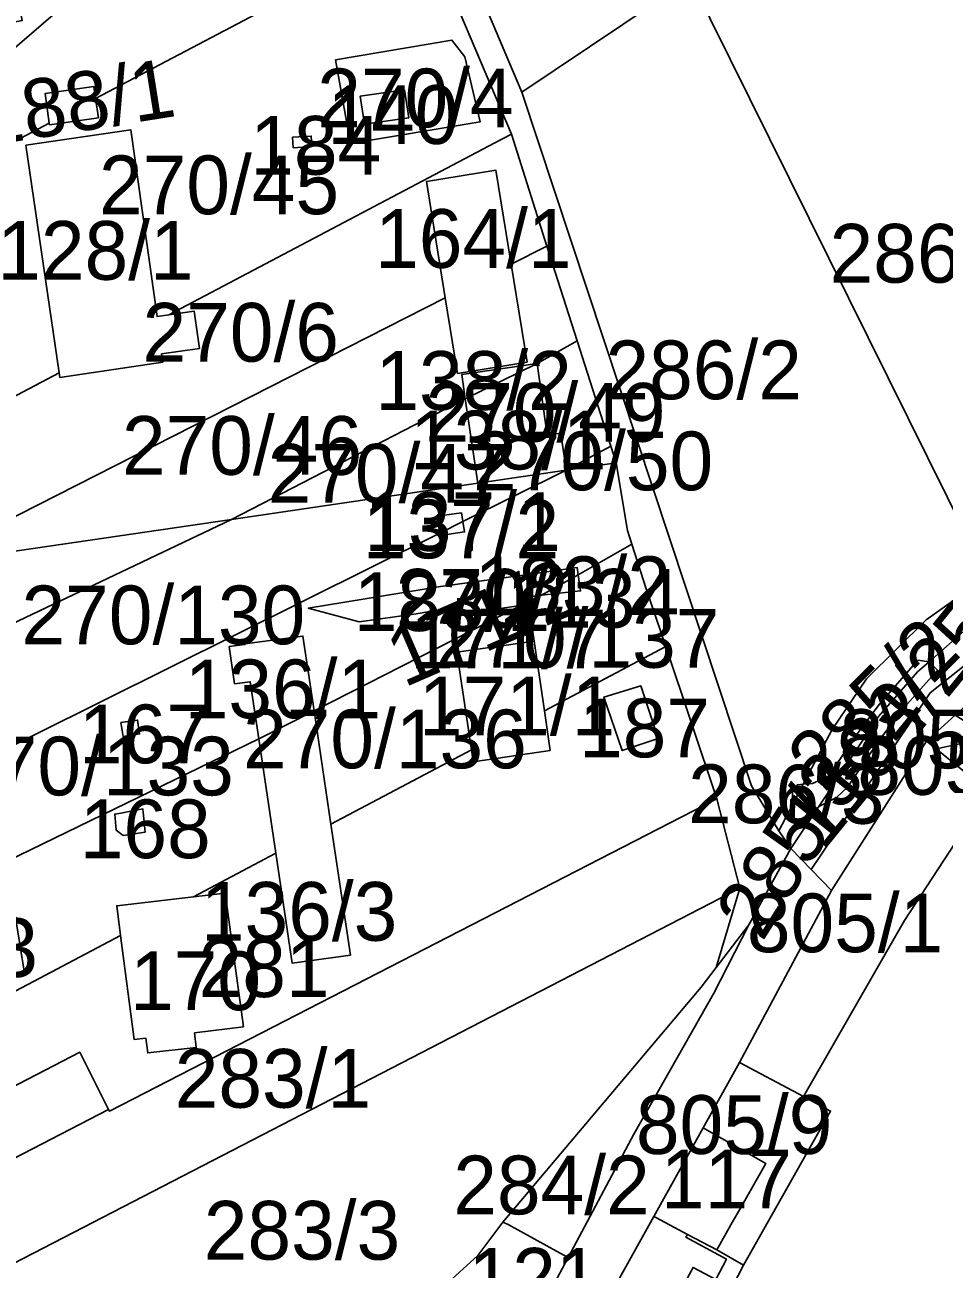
# Model space of a CAD drawing. Extents: x -623250 to -619626, y -1079612 to -1075424.
# Drawn here: x -621383.5 to -621226.9, y -1076913.6 to -1076701.7 of the extents above; entities that cross this region are included whole.
import ezdxf

# ---------------------------------------------------------------- set-up
doc = ezdxf.new("R2010")
doc.units = 0
for name, color, linetype in [('Hranice převzatá (k_ú_Džbánov - vnitřní obvod)', 7, 'Continuous'), ('Hranice šetřená (k_ú_Džbánov - vnitřní obvod)', 7, 'Continuous'), ('Parcela nároku', 7, 'Continuous'), ('Parcelní číslo', 7, 'Continuous'), ('Silnice III_35719', 7, 'Continuous')]:
    doc.layers.add(name, color=color, linetype=linetype)

msp = doc.modelspace()

# ---------------------------------------------------------------- linework, layer by layer
at = {"layer": 'Hranice převzatá (k_ú_Džbánov - vnitřní obvod)'}
msp.add_line((-621276.85, -1076943.57), (-621261.07, -1076912.95), dxfattribs=at)
msp.add_lwpolyline([(-621298.85, -1076713.1), (-621270.08, -1076693.81), (-621236.65, -1076671.5)], dxfattribs=at)
at = {"layer": 'Hranice šetřená (k_ú_Džbánov - vnitřní obvod)'}
msp.add_lwpolyline([(-621298.85, -1076713.1), (-621259.7, -1076831.32), (-621255.05, -1076838.97), (-621253, -1076841.99), (-621246.1, -1076849.15), (-621229.91, -1076823.66), (-621228.23, -1076825.01), (-621219.28, -1076832.25), (-621233.62, -1076854.22), (-621250.86, -1076884.25), (-621246.23, -1076886.72), (-621261.07, -1076912.95)], dxfattribs=at)
at = {"layer": 'Parcela nároku'}
for points in [[(-621322.96, -1076681.57), (-621319.95, -1076687.05), (-621371.44, -1076714.22), (-621371.74, -1076712.18), (-621380.06, -1076713.37), (-621379.35, -1076718.39), (-621402.49, -1076730.6), (-621403.83, -1076721.46), (-621388.56, -1076708.39), (-621376.66, -1076698.2), (-621392.01, -1076624.26), (-621356.72, -1076606.72), (-621328.57, -1076658.55), (-621315.63, -1076684.78), (-621316.6, -1076685.28), (-621319.64, -1076679.74)], [(-621388.71, -1076669.32), (-621390.43, -1076669.67), (-621383.95, -1076700.92), (-621413.69, -1076707.06), (-621426.54, -1076645.01), (-621426.15, -1076644.93), (-621426.9, -1076641.3), (-621443.58, -1076649.82), (-621442.17, -1076653.36), (-621427.19, -1076692.17), (-621425.37, -1076698.46), (-621424.67, -1076704.93), (-621425.04, -1076706.31), (-621423.47, -1076709.46), (-621412.67, -1076711.87), (-621388.56, -1076708.39), (-621376.66, -1076698.2), (-621392.01, -1076624.26), (-621418.24, -1076637.08), (-621412.96, -1076635.98), (-621411.73, -1076641.95), (-621396.81, -1076638.86), (-621391.28, -1076665.56), (-621389.61, -1076665.22)], [(-621310.32, -1076647.1), (-621318.13, -1076650.49), (-621326.18, -1076653.91), (-621314.99, -1076675.01), (-621298.85, -1076713.1), (-621270.08, -1076693.81), (-621273.77, -1076685.85), (-621291.69, -1076697.6), (-621297.85, -1076688.2), (-621290.86, -1076683.66), (-621286.12, -1076690.97), (-621282.78, -1076688.79)], [(-621182.7, -1076775.26), (-621234.22, -1076669.88), (-621236.65, -1076671.5), (-621270.08, -1076693.81), (-621219.61, -1076795.68)], [(-621319.95, -1076687.05), (-621319.59, -1076687.71), (-621316.26, -1076685.88), (-621316.6, -1076685.28), (-621315.63, -1076684.78), (-621300.62, -1076720.28), (-621303.43, -1076721.77), (-621358.98, -1076751.06), (-621360.99, -1076751.34), (-621365.44, -1076719.56), (-621383.33, -1076722.15), (-621377.65, -1076760.91), (-621397.07, -1076771.16), (-621402.49, -1076730.6), (-621379.35, -1076718.39), (-621379.3, -1076718.68), (-621370.98, -1076717.49), (-621371.44, -1076714.22)], [(-621270.08, -1076693.81), (-621298.85, -1076713.1), (-621259.7, -1076831.32), (-621255.05, -1076838.97), (-621252.76, -1076834.62), (-621252.74, -1076832.26), (-621251.88, -1076831.12), (-621250.88, -1076831.04), (-621245.98, -1076821.72), (-621240.09, -1076813.05), (-621229.96, -1076803.04), (-621219.61, -1076795.68)], [(-621308.54, -1076707.11), (-621305.93, -1076718.15), (-621328.01, -1076721.86), (-621330.58, -1076707.59), (-621310.75, -1076704.26)], [(-621330.58, -1076707.59), (-621328.01, -1076721.86), (-621305.93, -1076718.15), (-621308.54, -1076707.11), (-621310.75, -1076704.26)], [(-621371.44, -1076714.22), (-621370.98, -1076717.49), (-621379.3, -1076718.68), (-621379.35, -1076718.39), (-621380.06, -1076713.37), (-621371.74, -1076712.18)], [(-621318.83, -1076712.73), (-621318.11, -1076717.52), (-621325.64, -1076718.58), (-621326.4, -1076713.81)], [(-621325.64, -1076718.58), (-621326.4, -1076713.81), (-621318.83, -1076712.73), (-621318.11, -1076717.52)], [(-621294.55, -1076739.35), (-621300.62, -1076720.28), (-621303.43, -1076721.77), (-621358.98, -1076751.06), (-621354.64, -1076750.45), (-621353.76, -1076756.8), (-621360.2, -1076757.7), (-621360, -1076759.14), (-621377.55, -1076761.72), (-621377.65, -1076760.91), (-621397.07, -1076771.16), (-621395.87, -1076781.11), (-621394.56, -1076790.17), (-621311.88, -1076748.16), (-621315.1, -1076728.34), (-621303.25, -1076726.41), (-621300.64, -1076742.44)], [(-621354.64, -1076750.45), (-621353.76, -1076756.8), (-621360.2, -1076757.7), (-621360, -1076759.14), (-621377.55, -1076761.72), (-621377.65, -1076760.91), (-621383.33, -1076722.15), (-621365.44, -1076719.56), (-621360.99, -1076751.34), (-621358.98, -1076751.06)], [(-621334.72, -1076720.59), (-621334.6, -1076722.37), (-621337.79, -1076722.59), (-621337.89, -1076720.81)], [(-621337.79, -1076722.59), (-621334.6, -1076722.37), (-621334.72, -1076720.59), (-621337.89, -1076720.81)], [(-621297.93, -1076759.11), (-621300.64, -1076742.44), (-621303.25, -1076726.41), (-621315.1, -1076728.34), (-621311.88, -1076748.16), (-621309.78, -1076761.04)], [(-621309.78, -1076761.04), (-621297.93, -1076759.11), (-621300.64, -1076742.44), (-621294.55, -1076739.35), (-621289.41, -1076755.49), (-621296.21, -1076759.36), (-621309.08, -1076761.24), (-621308.47, -1076765.34), (-621348.32, -1076785.92), (-621394.2, -1076792.65), (-621394.56, -1076790.17), (-621311.88, -1076748.16)], [(-621296.21, -1076759.36), (-621289.41, -1076755.49), (-621283.67, -1076773.41), (-621291.29, -1076777.54), (-621292.22, -1076771.24), (-621294.53, -1076771.57)], [(-621309.08, -1076761.24), (-621296.21, -1076759.36), (-621308.47, -1076765.34)], [(-621296.21, -1076759.36), (-621294.53, -1076771.57), (-621292.22, -1076771.24), (-621291.29, -1076777.54), (-621293.61, -1076777.88), (-621306.32, -1076779.74), (-621308.47, -1076765.34)], [(-621348.32, -1076785.92), (-621308.47, -1076765.34), (-621306.32, -1076779.74)], [(-621291.29, -1076777.54), (-621283.67, -1076773.41), (-621282.75, -1076776.26)], [(-621348.32, -1076785.92), (-621306.32, -1076779.74), (-621293.61, -1076777.88), (-621291.29, -1076777.54), (-621308.88, -1076786.29), (-621309.12, -1076784.79), (-621313.33, -1076785.36), (-621312.82, -1076788.25), (-621393.46, -1076828.35), (-621394.99, -1076818.77), (-621390.79, -1076818.12), (-621391.71, -1076812.19), (-621395.9, -1076812.86), (-621409.24, -1076814.91)], [(-621308.88, -1076786.29), (-621309.12, -1076784.79), (-621313.33, -1076785.36), (-621312.82, -1076788.25)], [(-621406.62, -1076795.93), (-621402.17, -1076793.81), (-621398.87, -1076793.33), (-621394.2, -1076792.65), (-621348.32, -1076785.92), (-621409.24, -1076814.91), (-621431.24, -1076827.04), (-621432.51, -1076818.29), (-621437.84, -1076818.95), (-621449.89, -1076820.81), (-621447.66, -1076836.1), (-621458.65, -1076841.61), (-621461.29, -1076823.62), (-621412.18, -1076798.59), (-621412.05, -1076799.5), (-621406.26, -1076798.56)], [(-621308.59, -1076788.05), (-621308.88, -1076786.29), (-621312.82, -1076788.25), (-621312.75, -1076788.66)], [(-621277.63, -1076797.72), (-621274.32, -1076807.57), (-621294.99, -1076818.54), (-621296.72, -1076806.64), (-621297.63, -1076800.41), (-621297.69, -1076799.94), (-621295.5, -1076798.83), (-621288.82, -1076798.08), (-621289.22, -1076795.36), (-621280.1, -1076790.12)], [(-621296.99, -1076795.19), (-621312.68, -1076797.31), (-621335.21, -1076801.02), (-621326.55, -1076803.37), (-621316.86, -1076802.02), (-621312.17, -1076801.19), (-621310.98, -1076801.02), (-621310.83, -1076802.29), (-621298.99, -1076800.6), (-621297.63, -1076800.41), (-621297.69, -1076799.94), (-621297.79, -1076799.13), (-621296.46, -1076798.94), (-621295.5, -1076798.83), (-621289.22, -1076795.36), (-621289.41, -1076794.08)], [(-621288.82, -1076798.08), (-621289.22, -1076795.36), (-621295.5, -1076798.83)], [(-621250.88, -1076831.04), (-621245.98, -1076821.72), (-621240.09, -1076813.05), (-621229.96, -1076803.04), (-621219.61, -1076795.68), (-621217.62, -1076799.73), (-621229.47, -1076810.15), (-621231.36, -1076809.88), (-621237.9, -1076817.41), (-621241.71, -1076822.45), (-621246.57, -1076829.67), (-621249.32, -1076830.92)], [(-621297.79, -1076799.13), (-621296.46, -1076798.94), (-621295.5, -1076798.83), (-621297.69, -1076799.94)], [(-621310.83, -1076802.29), (-621298.99, -1076800.6), (-621310.23, -1076806.32)], [(-621310.23, -1076806.32), (-621298.99, -1076800.6), (-621297.63, -1076800.41), (-621296.72, -1076806.64), (-621309.9, -1076808.54)], [(-621346.03, -1076807.08), (-621336.12, -1076805.78), (-621334.23, -1076818.52), (-621343.65, -1076823.28), (-621345.1, -1076813.57), (-621347.76, -1076813.91), (-621348.68, -1076807.58), (-621346.01, -1076807.23)], [(-621307.42, -1076825.14), (-621309.9, -1076808.54), (-621310.23, -1076806.32), (-621334.23, -1076818.52), (-621331.36, -1076837.85)], [(-621294.99, -1076818.54), (-621294.01, -1076825.27), (-621307.11, -1076827.22), (-621307.42, -1076825.14), (-621309.9, -1076808.54), (-621296.72, -1076806.64)], [(-621241.71, -1076822.45), (-621246.57, -1076829.67), (-621249.32, -1076830.92), (-621250.88, -1076831.04), (-621252.76, -1076834.62), (-621255.05, -1076838.97), (-621253, -1076841.99), (-621248.24, -1076834.81), (-621238.1, -1076819.51), (-621231.41, -1076811.86), (-621229.47, -1076810.15), (-621231.36, -1076809.88), (-621237.9, -1076817.41)], [(-621231.41, -1076811.86), (-621229.47, -1076810.15), (-621228.04, -1076811.58), (-621233.71, -1076817.96), (-621237.89, -1076823.44), (-621243.38, -1076831.55), (-621245.25, -1076833.3), (-621248.24, -1076834.81), (-621238.1, -1076819.51)], [(-621275.6, -1076823.26), (-621278.55, -1076814.27), (-621284.86, -1076816.17), (-621281.73, -1076825.28)], [(-621281.73, -1076825.28), (-621275.6, -1076823.26), (-621278.55, -1076814.27), (-621284.86, -1076816.17)], [(-621328.05, -1076860.12), (-621331.36, -1076837.85), (-621334.23, -1076818.52), (-621343.65, -1076823.28), (-621340.75, -1076842.78), (-621337.96, -1076861.51)], [(-621364.3, -1076820.1), (-621367.15, -1076820.51), (-621366.78, -1076822.87), (-621363.96, -1076822.46)], [(-621366.78, -1076822.87), (-621363.96, -1076822.46), (-621364.3, -1076820.1), (-621367.15, -1076820.51)], [(-621229.91, -1076823.66), (-621225, -1076819.24), (-621221.18, -1076821.67), (-621223.92, -1076824.07), (-621228.23, -1076825.01)], [(-621221.18, -1076821.67), (-621223.92, -1076824.07), (-621228.23, -1076825.01), (-621219.28, -1076832.25), (-621214.06, -1076826.2)], [(-621442.1, -1076874.3), (-621462.22, -1076885.24), (-621454.35, -1076902.86), (-621367.2, -1076856.77), (-621367.86, -1076851.73), (-621354.77, -1076850.19), (-621340.75, -1076842.78), (-621343.65, -1076823.28), (-621386.62, -1076844.18), (-621383.59, -1076863.23), (-621387.8, -1076863.85), (-621401.16, -1076865.82), (-621403.2, -1076852.98), (-621425.73, -1076865.1), (-621423.89, -1076877.78), (-621429.15, -1076878.6), (-621441.23, -1076880.28)], [(-621229.91, -1076823.66), (-621228.23, -1076825.01), (-621219.28, -1076832.25), (-621233.62, -1076854.22), (-621250.86, -1076884.25), (-621261.77, -1076878.43), (-621246.1, -1076849.15)], [(-621250.88, -1076831.04), (-621251.88, -1076831.12), (-621252.74, -1076832.26), (-621252.76, -1076834.62)], [(-621265.61, -1076833.49), (-621261.7, -1076848.72), (-621388.91, -1076914.43), (-621400.8, -1076920.49), (-621408.16, -1076906.52), (-621369.25, -1076886.43), (-621369.11, -1076886.7)], [(-621363.39, -1076835.24), (-621367.13, -1076835.94), (-621368.18, -1076836.1), (-621367.92, -1076838.85), (-621366.76, -1076839.78), (-621362.98, -1076839.17)], [(-621368.18, -1076836.1), (-621367.92, -1076838.85), (-621366.76, -1076839.78), (-621362.98, -1076839.17), (-621363.39, -1076835.24), (-621367.13, -1076835.94)], [(-621388.91, -1076914.43), (-621261.7, -1076848.72), (-621265.74, -1076862.26), (-621268.27, -1076865.58), (-621302.1, -1076905.64), (-621306.34, -1076911.31), (-621320.09, -1076923.81), (-621321.03, -1076924.46), (-621358.9, -1076950.67), (-621371.51, -1076935.3)], [(-621354.31, -1076875.88), (-621354.59, -1076873.38), (-621346.27, -1076872.33), (-621349.37, -1076849.56), (-621354.77, -1076850.19), (-621367.86, -1076851.73), (-621367.2, -1076856.77), (-621364.88, -1076874.53), (-621362.88, -1076874.3), (-621362.57, -1076876.81)], [(-621302.1, -1076905.64), (-621268.27, -1076865.58), (-621265.74, -1076862.26), (-621260.18, -1076854.95), (-621266.21, -1076866.74), (-621279.76, -1076890.66), (-621290.94, -1076911.65), (-621292.93, -1076910.56), (-621301.18, -1076906.02)], [(-621374.14, -1076876.68), (-621369.25, -1076886.43), (-621408.16, -1076906.52), (-621418.09, -1076911.65), (-621423.06, -1076902.04)], [(-621265.64, -1076910.36), (-621263.22, -1076906.1), (-621261.31, -1076902.73), (-621257.27, -1076895.61), (-621262.24, -1076892.79), (-621267.25, -1076889.96), (-621267.95, -1076889.56), (-621261.77, -1076878.43), (-621250.86, -1076884.25), (-621246.23, -1076886.72), (-621261.07, -1076912.95)], [(-621262.24, -1076892.79), (-621257.27, -1076895.61), (-621261.31, -1076902.73), (-621263.22, -1076906.1), (-621265.64, -1076910.36), (-621270.64, -1076907.72), (-621275.91, -1076904.88), (-621276.33, -1076904.65), (-621267.95, -1076889.56), (-621267.25, -1076889.96)], [(-621263.97, -1076911.91), (-621270.87, -1076908.16), (-621270.64, -1076907.72), (-621275.91, -1076904.88), (-621276.33, -1076904.65), (-621286.38, -1076922.74), (-621285.9, -1076923.02), (-621277.33, -1076927.74), (-621271.34, -1076916.49), (-621269.65, -1076913.33), (-621265.81, -1076915.39)], [(-621320.09, -1076923.81), (-621321.03, -1076924.46), (-621298.1, -1076925.1), (-621290.94, -1076911.65), (-621292.93, -1076910.56), (-621301.18, -1076906.02), (-621302.1, -1076905.64), (-621306.34, -1076911.31)], [(-621293.22, -1076935.57), (-621286.38, -1076922.74), (-621285.9, -1076923.02), (-621277.33, -1076927.74), (-621271.34, -1076916.49), (-621269.65, -1076913.33), (-621265.81, -1076915.39), (-621263.97, -1076911.91), (-621270.87, -1076908.16), (-621270.64, -1076907.72), (-621265.64, -1076910.36), (-621261.07, -1076912.95), (-621276.85, -1076943.57), (-621281.03, -1076941.69)]]:
    msp.add_lwpolyline(points, close=True, dxfattribs=at)
for points in [[(-621314.99, -1076675.01), (-621298.85, -1076713.1), (-621259.7, -1076831.32), (-621255.05, -1076838.97), (-621253, -1076841.99), (-621260.18, -1076854.95), (-621265.74, -1076862.26), (-621261.7, -1076848.72), (-621265.61, -1076833.49), (-621274.32, -1076807.57), (-621277.63, -1076797.72), (-621280.1, -1076790.12), (-621280.86, -1076787.78), (-621282.75, -1076776.26), (-621283.67, -1076773.41), (-621289.41, -1076755.49), (-621294.55, -1076739.35), (-621300.62, -1076720.28), (-621315.63, -1076684.78)], [(-621298.1, -1076925.1), (-621290.94, -1076911.65), (-621279.76, -1076890.66), (-621266.21, -1076866.74), (-621260.18, -1076854.95), (-621253, -1076841.99), (-621248.24, -1076834.81), (-621245.25, -1076833.3), (-621243.38, -1076831.55), (-621237.89, -1076823.44), (-621233.71, -1076817.96), (-621228.04, -1076811.58), (-621229.47, -1076810.15), (-621217.62, -1076799.73), (-621181.63, -1076777.39), (-621155.85, -1076761.71), (-621129.68, -1076745.79), (-621112.96, -1076735.62), (-621096.81, -1076726.52), (-621071.03, -1076711.98), (-621068.06, -1076710.36), (-621036.03, -1076693.96)], [(-621020.64, -1076702.21), (-621049.01, -1076717.2), (-621091.99, -1076741.17), (-621124.81, -1076761.52), (-621185.25, -1076804.59), (-621194.09, -1076808.13), (-621205.54, -1076816.32), (-621214.06, -1076826.2), (-621219.28, -1076832.25), (-621233.62, -1076854.22), (-621250.86, -1076884.25), (-621246.23, -1076886.72), (-621261.07, -1076912.95), (-621276.85, -1076943.57)], [(-621037.06, -1076706.24), (-621051.48, -1076712.79), (-621097.56, -1076737.19), (-621143.54, -1076764.96), (-621164.84, -1076778.36), (-621213.8, -1076809.17), (-621225, -1076819.24), (-621229.91, -1076823.66), (-621246.1, -1076849.15), (-621261.77, -1076878.43), (-621267.95, -1076889.56), (-621276.33, -1076904.65), (-621286.38, -1076922.74)], [(-621393.46, -1076828.35), (-621312.82, -1076788.25), (-621312.75, -1076788.66), (-621308.59, -1076788.05), (-621308.88, -1076786.29), (-621291.29, -1076777.54), (-621282.75, -1076776.26), (-621280.86, -1076787.78), (-621280.1, -1076790.12), (-621289.22, -1076795.36), (-621289.41, -1076794.08), (-621296.99, -1076795.19), (-621312.68, -1076797.31), (-621335.21, -1076801.02), (-621326.55, -1076803.37), (-621316.86, -1076802.02), (-621312.17, -1076801.19), (-621310.98, -1076801.02), (-621310.83, -1076802.29), (-621310.23, -1076806.32), (-621334.23, -1076818.52), (-621336.12, -1076805.78), (-621346.03, -1076807.08), (-621346.01, -1076807.23), (-621348.68, -1076807.58), (-621347.76, -1076813.91), (-621345.1, -1076813.57), (-621343.65, -1076823.28), (-621386.62, -1076844.18)], [(-621454.35, -1076902.86), (-621367.2, -1076856.77), (-621364.88, -1076874.53), (-621362.88, -1076874.3), (-621362.57, -1076876.81), (-621354.31, -1076875.88), (-621354.59, -1076873.38), (-621346.27, -1076872.33), (-621349.37, -1076849.56), (-621354.77, -1076850.19), (-621340.75, -1076842.78), (-621337.96, -1076861.51), (-621328.05, -1076860.12), (-621331.36, -1076837.85), (-621307.42, -1076825.14), (-621307.11, -1076827.22), (-621294.01, -1076825.27), (-621294.99, -1076818.54), (-621274.32, -1076807.57), (-621265.61, -1076833.49), (-621369.11, -1076886.7), (-621369.25, -1076886.43), (-621374.14, -1076876.68), (-621423.06, -1076902.04)]]:
    msp.add_lwpolyline(points, dxfattribs=at)
at = {"layer": 'Silnice III_35719'}
for p, q in [((-621229.29, -1076815.48), (-621197.55, -1076790.14)), ((-621249.55, -1076845.57), (-621229.29, -1076815.48))]:
    msp.add_line(p, q, dxfattribs=at)

# ---------------------------------------------------------------- texts
at = {"layer": 'Parcelní číslo'}
for s, rotation, p in [('188/1', 9.037, (-621390.49, -1076722.4)), ('171/2', 23.4607, (-621318.93, -1076814.62)), ('1184/25', 50.936, (-621247.56, -1076842.63)), ('285/2', 45, (-621247.36, -1076832.59)), ('805/11', 359.7602, (-621244.75, -1076828.24)), ('285/3', 57.8687, (-621257.89, -1076858.04)), ('286/3', 359.7602, (-621270.53, -1076837.63))]:
    msp.add_text(s, height=10, rotation=rotation, dxfattribs=at).set_placement(p)
for s, p in [('270/4', (-621333.69, -1076719.11)), ('140', (-621331.96, -1076721.94)), ('184', (-621345.1, -1076727.18)), ('270/45', (-621370.87, -1076733.91)), ('164/1', (-621323.83, -1076743.05)), ('128/1', (-621388.21, -1076745.08)), ('286/1', (-621246.41, -1076745.57)), ('270/6', (-621363.46, -1076759.03)), ('286/2', (-621284.59, -1076765.43)), ('138/2', (-621323.79, -1076767.24)), ('270/49', (-621315.25, -1076772.67)), ('270/46', (-621366.96, -1076778.31)), ('138/1', (-621317.87, -1076777.39)), ('270/50', (-621307.14, -1076780.94)), ('270/47', (-621342.15, -1076783.05)), ('137/2', (-621325.94, -1076792.54)), ('137/1', (-621325.67, -1076791.27)), ('183/2', (-621306.89, -1076802.21)), ('183/1', (-621327.47, -1076804.92)), ('270/134', (-621320.35, -1076804.35)), ('270/130', (-621384.08, -1076807.18)), ('171/7', (-621317.88, -1076811.28)), ('270/137', (-621313.52, -1076811.17)), ('136/1', (-621356.27, -1076819.78)), ('171/1', (-621316.38, -1076822.68)), ('187', (-621289.09, -1076826.44)), ('167', (-621374.29, -1076827.45)), ('270/136', (-621346.33, -1076828.31)), ('270/133', (-621396.24, -1076832.92)), ('805/2', (-621241.68, -1076832.83)), ('168', (-621374.15, -1076843.62)), ('136/3', (-621353.51, -1076857.68)), ('805/1', (-621260.5, -1076859.64)), ('129/3', (-621414.74, -1076863.86)), ('281', (-621353.9, -1076867.28)), ('170', (-621365.58, -1076869.51)), ('283/1', (-621357.97, -1076886.13)), ('805/9', (-621279.4, -1076894.01)), ('284/2', (-621310.51, -1076904.3)), ('117', (-621275.14, -1076903.3)), ('283/3', (-621353.02, -1076912.02)), ('121', (-621307.91, -1076920.03))]:
    msp.add_text(s, height=10, dxfattribs=at).set_placement(p)

doc.saveas('drawing.dxf')
